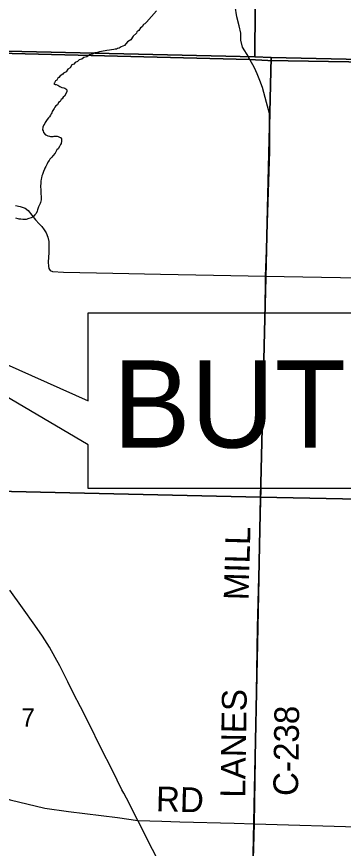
# Model space of a CAD drawing. Extents: x 0 to 34, y 0 to 22.
# Drawn here: x 5.846 to 6.595, y 15.693 to 17.601 of the extents above; entities that cross this region are included whole.
import ezdxf

# ---------------------------------------------------------------- set-up
doc = ezdxf.new("R2010")
doc.units = 0
for name, color, linetype in [('Default', 7, 'Continuous'), ('GM_X_County_Road', 7, 'Continuous'), ('GM_X_County_Road_Text', 7, 'Continuous'), ('GM_X_Minor_River', 7, 'Continuous'), ('GM_X_Section', 7, 'Continuous'), ('GM_X_Section_Text', 7, 'Continuous'), ('GM_X_Township_Road', 7, 'Continuous'), ('GM_X_US_Route', 7, 'Continuous'), ('SH_Text', 7, 'Continuous')]:
    doc.layers.add(name, color=color, linetype=linetype)

msp = doc.modelspace()

# ---------------------------------------------------------------- linework, layer by layer
at = {"layer": 'Default'}
msp.add_lwpolyline([(8.8, 17.4621), (8.8, 20.2361), (5.4689, 20.2361), (5.4688, 20.2302), (5.4607, 19.86), (5.4543, 19.5706), (5.4479, 19.3941), (5.3804, 17.5273), (6.3799, 17.5028), (6.4218, 17.5004), (7.3975, 17.4842), (8.3778, 17.4688), (8.5283, 17.4669), (8.6626, 17.4644)], close=True, dxfattribs=at)
msp.add_lwpolyline([(8.8, 13.4361), (8.8, 17.4621), (8.6626, 17.4644), (8.5283, 17.4669), (8.3778, 17.4688), (7.3975, 17.4842), (6.4218, 17.5004), (6.3799, 17.5028), (5.3804, 17.5273), (5.3798, 17.5031), (5.3707, 17.1134), (5.3682, 17.0062)], dxfattribs=at)
at = {"layer": 'GM_X_County_Road'}
msp.add_line((6.4153, 16.9213), (6.4164, 17.0054), dxfattribs=at)
for points in [[(6.3784, 17.5065), (6.378, 17.5075), (6.3633, 17.5306), (6.3595, 17.5469), (6.3597, 17.5629), (6.3562, 17.5799), (6.3507, 17.6005), (6.3469, 17.6248)], [(6.4164, 17.0054), (6.4199, 17.1051), (6.4264, 17.2924), (6.4261, 17.3462), (6.4253, 17.3786), (6.419, 17.4035), (6.4097, 17.438), (6.4035, 17.4541), (6.3974, 17.4693), (6.391, 17.4832), (6.3802, 17.5022), (6.3784, 17.5065)], [(6.4164, 17.0054), (6.7166, 17.0006)], [(6.381, 15.3157), (6.3812, 15.3469), (6.3814, 15.3755), (6.3822, 15.397), (6.3833, 15.4772), (6.3909, 15.75), (6.3977, 16.2002), (6.4064, 16.5183)], [(5.3492, 15.9409), (5.4463, 15.9156), (5.558, 15.8841), (5.6405, 15.8603), (5.7937, 15.8156), (5.8306, 15.8045), (5.9105, 15.7856), (5.9646, 15.7778), (6.0771, 15.7639), (6.1234, 15.7574)], [(6.1234, 15.7574), (6.1785, 15.7557), (6.2198, 15.7544), (6.3447, 15.7512), (6.3909, 15.75), (6.6519, 15.7417), (6.8651, 15.7373), (7.154, 15.7313), (7.366, 15.727), (7.6635, 15.7206), (8.047, 15.7149), (8.3634, 15.7062), (8.574, 15.7023), (8.8, 15.699)]]:
    msp.add_lwpolyline(points, dxfattribs=at)
at = {"layer": 'GM_X_Minor_River'}
for points in [[(6.1666, 17.6138), (6.1432, 17.5882), (6.1393, 17.5845), (6.1362, 17.5827), (6.1334, 17.5775), (6.1296, 17.5749), (6.126, 17.5689), (6.1214, 17.5656), (6.1202, 17.5626), (6.1132, 17.5563), (6.1073, 17.5473), (6.0999, 17.543), (6.0933, 17.5344), (6.0856, 17.5315), (6.081, 17.5286), (6.0771, 17.5276), (6.0744, 17.5265), (6.0714, 17.5262), (6.0683, 17.5251), (6.063, 17.5249), (6.0584, 17.5239), (6.0527, 17.5232), (6.0485, 17.5226), (6.0439, 17.5219), (6.0405, 17.5209), (6.0359, 17.5202), (6.0313, 17.5188), (6.0248, 17.5175), (6.0194, 17.5146), (6.0125, 17.5128), (6.0067, 17.5088), (5.9998, 17.5071), (5.9948, 17.5034), (5.9891, 17.5016), (5.9852, 17.4979), (5.9798, 17.4958), (5.9767, 17.4921), (5.9724, 17.4899), (5.9681, 17.4836), (5.9627, 17.4806), (5.9588, 17.4743), (5.953, 17.4714), (5.9514, 17.4688), (5.9452, 17.4647), (5.9421, 17.4614), (5.9398, 17.4596), (5.9374, 17.4554), (5.9347, 17.4532), (5.9327, 17.4491), (5.9307, 17.4469), (5.9341, 17.4453), (5.9364, 17.4448), (5.9402, 17.4432), (5.9443, 17.4408), (5.9492, 17.4384), (5.9537, 17.4372), (5.9564, 17.4364), (5.9586, 17.4348), (5.9605, 17.4325), (5.9604, 17.4294), (5.9588, 17.4253), (5.9552, 17.4182), (5.9521, 17.416), (5.9501, 17.4126), (5.9474, 17.4108), (5.9454, 17.4062), (5.9419, 17.4037), (5.9391, 17.3984), (5.9357, 17.3962), (5.9333, 17.3933), (5.9317, 17.3903), (5.9298, 17.3876), (5.9274, 17.3831), (5.9262, 17.3805), (5.9246, 17.3775), (5.9234, 17.3749), (5.921, 17.3708), (5.9187, 17.3689), (5.9159, 17.3652), (5.9128, 17.3603), (5.9108, 17.3581), (5.9104, 17.3555), (5.908, 17.3525), (5.906, 17.3472), (5.9051, 17.3412), (5.9066, 17.3388), (5.9072, 17.3354), (5.9117, 17.33), (5.9143, 17.3288), (5.9169, 17.3272), (5.9207, 17.3263), (5.923, 17.3259)], [(5.923, 17.3259), (5.9264, 17.3258), (5.9295, 17.3261), (5.9318, 17.3264), (5.9344, 17.3264), (5.9382, 17.3263), (5.9409, 17.3258), (5.9439, 17.3242), (5.9461, 17.3234), (5.9484, 17.3203), (5.9486, 17.3154), (5.9473, 17.3097), (5.9458, 17.3075), (5.9442, 17.3033), (5.9406, 17.2974), (5.9379, 17.2951), (5.9355, 17.291), (5.9339, 17.2876), (5.9288, 17.2817), (5.9265, 17.2783), (5.9218, 17.2739), (5.9202, 17.2709), (5.9174, 17.2668), (5.9158, 17.263), (5.9127, 17.2574), (5.9099, 17.2529), (5.9095, 17.2506), (5.9071, 17.2458), (5.9066, 17.2431), (5.905, 17.2386), (5.9034, 17.236), (5.9022, 17.2307), (5.9017, 17.2284), (5.9008, 17.2235), (5.9008, 17.2193), (5.9006, 17.211), (5.9011, 17.2034), (5.9011, 17.2007), (5.9013, 17.1939), (5.9016, 17.1889), (5.9015, 17.1866), (5.9018, 17.184), (5.9018, 17.1806), (5.9009, 17.1779), (5.9001, 17.1745), (5.8993, 17.1719), (5.8973, 17.1674), (5.8957, 17.1644), (5.8932, 17.158), (5.8928, 17.155), (5.89, 17.1493), (5.8873, 17.1464), (5.8837, 17.1415), (5.8787, 17.139), (5.8738, 17.138), (5.8676, 17.1358), (5.8653, 17.1355), (5.86, 17.1356), (5.8555, 17.1361), (5.8517, 17.1362), (5.8487, 17.1374), (5.8437, 17.1383)]]:
    msp.add_lwpolyline(points, dxfattribs=at)
at = {"layer": 'GM_X_Section'}
for points in [[(5.4246, 18.5313), (6.3991, 18.5175), (6.392, 17.5084), (5.3894, 17.5316)], [(6.3991, 18.5175), (7.3731, 18.5048), (7.3567, 17.4861), (6.4295, 17.5071), (6.392, 17.5084)], [(5.3894, 17.5316), (6.392, 17.5084), (6.4295, 17.5071), (6.4046, 16.4989), (5.3619, 16.5226)], [(6.4295, 17.5071), (7.3567, 17.4861), (7.3988, 17.4855), (7.3827, 16.4789), (6.4046, 16.4989)], [(5.3619, 16.5226), (6.4046, 16.4989), (6.384, 15.4928), (5.3374, 15.5147)], [(6.4046, 16.4989), (7.3827, 16.4789), (7.3639, 15.4717), (6.384, 15.4928)]]:
    msp.add_lwpolyline(points, close=True, dxfattribs=at)
at = {"layer": 'GM_X_Township_Road'}
msp.add_lwpolyline([(5.8426, 17.1673), (5.8537, 17.1656), (5.865, 17.1612), (5.8718, 17.1565), (5.8891, 17.1345), (5.8969, 17.1258), (5.9032, 17.1195), (5.909, 17.1122), (5.9131, 17.1049), (5.9169, 17.0949), (5.9192, 17.0849), (5.9191, 17.0598), (5.9181, 17.0375), (5.9183, 17.0283), (5.9194, 17.023), (5.9226, 17.0184), (5.9279, 17.0162), (5.9529, 17.0148), (6.0663, 17.0128), (6.1757, 17.0103), (6.2969, 17.0077), (6.4164, 17.0054)], dxfattribs=at)
at = {"layer": 'GM_X_US_Route'}
for points in [[(6.0913, 15.8199), (6.0871, 15.8275), (6.0657, 15.8716), (6.0389, 15.9238), (6.0117, 15.9788), (5.9923, 16.0179), (5.9759, 16.0488), (5.9627, 16.075), (5.9445, 16.1118), (5.9342, 16.1309), (5.9207, 16.1551), (5.9045, 16.1797), (5.887, 16.2054), (5.8588, 16.2451), (5.8298, 16.2857)], [(6.376, 15.2605), (6.3735, 15.2656), (6.3662, 15.2792), (6.3541, 15.3023), (6.3357, 15.3397), (6.3226, 15.3664), (6.3132, 15.3838), (6.3019, 15.407), (6.2884, 15.433), (6.2707, 15.4677), (6.2471, 15.5137), (6.2245, 15.5577), (6.2059, 15.5953), (6.1832, 15.6397), (6.1572, 15.6907), (6.1234, 15.7574), (6.0973, 15.8089), (6.0913, 15.8199)]]:
    msp.add_lwpolyline(points, dxfattribs=at)
at = {"layer": 'SH_Text'}
msp.add_lwpolyline([(6.0096, 16.9213), (7.8264, 16.9213), (7.8264, 16.5183), (6.0096, 16.5183), (6.0096, 16.619), (5.3006, 17.0363), (6.0096, 16.7198)], close=True, dxfattribs=at)

# ---------------------------------------------------------------- texts
at = {"layer": 'GM_X_County_Road_Text'}
for s, rotation, p in [('MILL', 88.3941, (6.3773, 16.2619)), ('LANES', 89.1481, (6.3698, 15.8092)), ('C-238', 89.1739, (6.4909, 15.8132)), ('RD', 358.5196, (6.1646, 15.7786))]:
    msp.add_text(s, height=0.05682, rotation=rotation, dxfattribs=at).set_placement(p)
at = {"layer": 'GM_X_Section_Text'}
msp.add_text('7', height=0.0419, rotation=0, dxfattribs=at).set_placement((5.8563, 15.9727))
at = {"layer": 'SH_Text'}
msp.add_text('BUT-27-1264', height=0.2, dxfattribs=at).set_placement((6.066, 16.6125))

doc.saveas('drawing.dxf')
